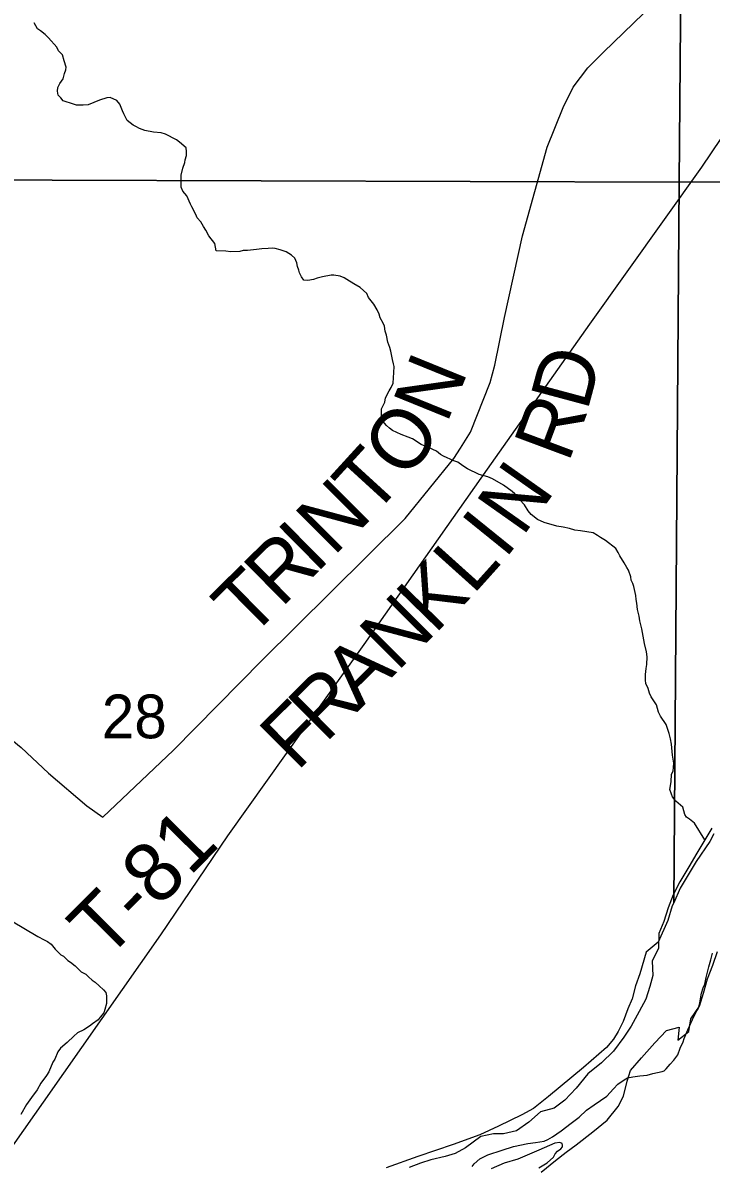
# Model space of a CAD drawing. Extents: x 0 to 34, y 0 to 22.
# Drawn here: x 4.533 to 5.191, y 16.193 to 17.286 of the extents above; entities that cross this region are included whole.
import ezdxf

# ---------------------------------------------------------------- set-up
doc = ezdxf.new("R2010")
doc.units = 0
for name, color, linetype in [('GM_X_Corporation', 7, 'Continuous'), ('GM_X_County_Road', 7, 'Continuous'), ('GM_X_County_Road_Text', 7, 'Continuous'), ('GM_X_Major_River', 7, 'Continuous'), ('GM_X_Minor_River', 7, 'Continuous'), ('GM_X_Rail_Line', 7, 'Continuous'), ('GM_X_Section_Text', 7, 'Continuous'), ('GM_X_Township_Road_Text', 7, 'Continuous')]:
    doc.layers.add(name, color=color, linetype=linetype)

msp = doc.modelspace()

# ---------------------------------------------------------------- linework, layer by layer
at = {"layer": 'GM_X_Corporation'}
msp.add_lwpolyline([(4.1647, 18.1352), (5.169, 18.1258), (5.1609, 17.1336), (4.1603, 17.1368)], close=True, dxfattribs=at)
for points in [[(5.3558, 17.3173), (5.3351, 17.273), (5.3274, 17.2459), (5.3164, 17.2139), (5.312, 17.203), (5.304, 17.1794), (5.3003, 17.1688), (5.2975, 17.1409), (5.2954, 17.1341), (5.1609, 17.1336), (5.169, 18.1258)], [(4.1603, 17.1368), (5.1609, 17.1336), (5.1556, 16.4443), (5.154, 16.4413), (5.15, 16.4274), (5.1408, 16.4067), (5.1292, 16.3971), (5.1231, 16.3764), (5.119, 16.3647), (5.1157, 16.3523), (5.1117, 16.3429), (5.1073, 16.3305), (5.1025, 16.3211), (5.0978, 16.3137), (5.0912, 16.3059), (5.0692, 16.2866), (5.0357, 16.2589), (5.0214, 16.2475), (5.0103, 16.2413), (4.9877, 16.2304), (4.9701, 16.2221), (4.9445, 16.2128), (4.9106, 16.2014), (4.8804, 16.1907)], [(5.1938, 16.5101), (5.1902, 16.503), (5.1769, 16.4836), (5.1616, 16.4582), (5.1556, 16.4443), (5.1609, 17.1336), (5.2954, 17.1341)], [(4.9626, 16.192), (4.9646, 16.1946), (4.97, 16.1994), (4.9777, 16.203), (4.9914, 16.2076), (5.0021, 16.2112), (5.0158, 16.2139), (5.0234, 16.2149), (5.0317, 16.2162), (5.0352, 16.2177), (5.0394, 16.2202), (5.0479, 16.2261), (5.0575, 16.2335), (5.0652, 16.239), (5.0721, 16.2457), (5.0794, 16.2508), (5.0856, 16.2552), (5.0914, 16.2593), (5.098, 16.2663), (5.1022, 16.2708), (5.108, 16.2748), (5.1114, 16.2766), (5.1164, 16.2777), (5.1232, 16.2787), (5.1301, 16.2793), (5.1354, 16.281), (5.1445, 16.2827), (5.1464, 16.2835), (5.1484, 16.2853), (5.1522, 16.2898), (5.1557, 16.2935), (5.1596, 16.2987), (5.1617, 16.3051), (5.1645, 16.3111), (5.1657, 16.3145), (5.1692, 16.3227), (5.1736, 16.3325), (5.1768, 16.3392), (5.1792, 16.3434), (5.1804, 16.3486), (5.1821, 16.3577), (5.1838, 16.363), (5.1853, 16.3663), (5.1866, 16.3727), (5.1891, 16.3829), (5.1911, 16.3897), (5.1928, 16.3961)], [(5.0266, 16.1906), (5.0343, 16.1953), (5.0405, 16.2009), (5.0421, 16.2039), (5.0444, 16.2065), (5.0475, 16.2087), (5.049, 16.2106), (5.0491, 16.2124), (5.0487, 16.214), (5.0465, 16.2148), (5.0419, 16.2141), (5.0266, 16.2076), (5.0064, 16.199), (4.9934, 16.1951), (4.9808, 16.1897)]]:
    msp.add_lwpolyline(points, dxfattribs=at)
at = {"layer": 'GM_X_County_Road'}
for points in [[(4.9515, 16.8793), (4.961, 16.8946), (4.98, 16.9422), (4.9843, 16.9585), (4.9937, 17.0044), (5.0109, 17.0823), (5.0344, 17.1672), (5.0498, 17.2051), (5.0592, 17.2245), (5.0732, 17.2431), (5.0882, 17.2581), (5.184, 17.3508)], [(4.6091, 16.5261), (4.6767, 16.5903), (4.7616, 16.6764), (4.827, 16.741), (4.8985, 16.8119), (4.9451, 16.8692), (4.9515, 16.8793)], [(3.7241, 16.5854), (3.9049, 16.5844), (4.0823, 16.5872), (4.1373, 16.59), (4.1698, 16.5932), (4.1944, 16.5988), (4.2309, 16.6077), (4.2593, 16.6207), (4.2867, 16.6246), (4.3422, 16.6223), (4.4404, 16.619), (4.5023, 16.6152), (4.5112, 16.6097), (4.522, 16.6), (4.5311, 16.5928), (4.5572, 16.5681), (4.5938, 16.5369), (4.6091, 16.5261)]]:
    msp.add_lwpolyline(points, dxfattribs=at)
at = {"layer": 'GM_X_Major_River'}
for points in [[(5.1919, 16.5155), (5.1853, 16.5046), (5.1778, 16.4918), (5.1699, 16.4787), (5.1613, 16.4644), (5.155, 16.452), (5.1502, 16.4395), (5.1461, 16.4263), (5.1413, 16.415), (5.141, 16.4007)], [(5.141, 16.4007), (5.135, 16.3884), (5.1357, 16.3747), (5.1328, 16.3641), (5.1287, 16.3521), (5.1226, 16.3401), (5.1147, 16.3263), (5.1079, 16.3158), (5.098, 16.3024), (5.0863, 16.291), (5.0735, 16.2807), (5.0621, 16.267), (5.0512, 16.2555), (5.0411, 16.2478), (5.0281, 16.2443), (5.0168, 16.2344), (5.0052, 16.226), (4.9926, 16.2233), (4.9831, 16.2232), (4.9709, 16.2205), (4.9561, 16.2098), (4.9465, 16.2044), (4.9369, 16.2016), (4.9232, 16.1982), (4.9132, 16.195), (4.9024, 16.1908)], [(5.0288, 16.1866), (5.0424, 16.1977), (5.0525, 16.2057), (5.0622, 16.2127), (5.0781, 16.2252), (5.092, 16.2362), (5.1023, 16.2492), (5.1075, 16.2593), (5.1109, 16.2736), (5.1142, 16.2838), (5.1248, 16.296), (5.1374, 16.3101), (5.1487, 16.322), (5.1609, 16.3251), (5.1595, 16.3129), (5.1699, 16.321), (5.1718, 16.3331), (5.1801, 16.3454), (5.1839, 16.3578), (5.188, 16.3714), (5.193, 16.3845), (5.1975, 16.3977)]]:
    msp.add_lwpolyline(points, dxfattribs=at)
at = {"layer": 'GM_X_Minor_River'}
for points in [[(4.572, 17.2499), (4.5705, 17.2556), (4.5667, 17.2595), (4.5652, 17.2629), (4.557, 17.2717), (4.554, 17.2751), (4.5495, 17.2786), (4.5465, 17.2805), (4.5435, 17.2862)], [(4.8875, 16.9599), (4.8864, 16.9641), (4.8849, 16.9721), (4.8838, 16.9755), (4.882, 16.9805), (4.8805, 16.9873), (4.8794, 16.9911), (4.8787, 16.996), (4.8776, 16.9987), (4.8746, 17.004), (4.8735, 17.0075), (4.8716, 17.0117), (4.8686, 17.017), (4.8634, 17.0235), (4.8619, 17.0273), (4.8555, 17.033), (4.8495, 17.0365), (4.8427, 17.0407), (4.8401, 17.0423), (4.8363, 17.0438), (4.8303, 17.0446), (4.8276, 17.0447), (4.8193, 17.0432), (4.8144, 17.0418), (4.8109, 17.0407), (4.8053, 17.0396), (4.8015, 17.04), (4.7992, 17.043), (4.7974, 17.0469), (4.7966, 17.0495), (4.7955, 17.0529), (4.7948, 17.0564), (4.7929, 17.0609), (4.7896, 17.064), (4.7847, 17.0671), (4.779, 17.069), (4.7741, 17.0702), (4.7715, 17.0706), (4.7673, 17.0703), (4.7612, 17.0699), (4.7563, 17.0692), (4.7476, 17.0685), (4.7435, 17.0682), (4.7404, 17.0675), (4.7317, 17.0672), (4.7268, 17.0676), (4.7177, 17.0681), (4.7163, 17.0749), (4.7107, 17.0825), (4.7077, 17.0879), (4.7054, 17.0913), (4.7028, 17.0959), (4.6994, 17.0997), (4.6983, 17.1028), (4.6942, 17.11), (4.6931, 17.1127), (4.6894, 17.1207), (4.6856, 17.1252), (4.6841, 17.1291), (4.6842, 17.1404), (4.6858, 17.1472), (4.6877, 17.1525), (4.6881, 17.1552), (4.6893, 17.1593), (4.6893, 17.1631), (4.689, 17.1666), (4.6826, 17.1719), (4.6796, 17.1742), (4.669, 17.1796), (4.6649, 17.1808), (4.6577, 17.1816), (4.6494, 17.1832), (4.6467, 17.184), (4.6441, 17.1852), (4.6407, 17.1871), (4.6381, 17.1883), (4.6324, 17.1929), (4.6309, 17.1959), (4.6291, 17.199), (4.628, 17.202), (4.6254, 17.2085), (4.6227, 17.2119), (4.6163, 17.2146), (4.6129, 17.2143), (4.6061, 17.2121), (4.5951, 17.2076), (4.5902, 17.2073), (4.5841, 17.2073), (4.5781, 17.2093), (4.5739, 17.2105), (4.5713, 17.2116), (4.569, 17.2143), (4.5664, 17.217), (4.5657, 17.2208), (4.5661, 17.2242), (4.568, 17.2283), (4.5711, 17.2325), (4.5726, 17.2378), (4.5738, 17.2412), (4.5742, 17.2438), (4.572, 17.2499)], [(5.1853, 16.5046), (5.1755, 16.5204), (5.1706, 16.5242), (5.1679, 16.5262), (5.1661, 16.5288), (5.1642, 16.5357), (5.1575, 16.5414), (5.1545, 16.5456), (5.1534, 16.5483), (5.1519, 16.5525), (5.1531, 16.56), (5.1535, 16.5672), (5.155, 16.5703), (5.1555, 16.5778), (5.1544, 16.5854), (5.1537, 16.5926), (5.1533, 16.5961), (5.1526, 16.601), (5.1511, 16.6063), (5.1497, 16.6109), (5.1482, 16.6147), (5.1429, 16.6227), (5.1411, 16.6265), (5.1392, 16.6337), (5.134, 16.6414), (5.1325, 16.6448), (5.131, 16.6494), (5.1288, 16.6539), (5.1284, 16.6573), (5.1285, 16.6627), (5.1293, 16.6683), (5.1297, 16.6721), (5.1301, 16.6797), (5.1294, 16.6843), (5.1276, 16.6922), (5.125, 16.7063), (5.1232, 16.7139), (5.1225, 16.7185), (5.121, 16.7249), (5.1203, 16.731), (5.1196, 16.7344), (5.1192, 16.7382), (5.1174, 16.7469), (5.1163, 16.7496), (5.1148, 16.753), (5.1144, 16.7561), (5.1122, 16.7625), (5.1107, 16.7652), (5.1081, 16.7694), (5.104, 16.7763), (5.1025, 16.7793), (5.1002, 16.7831), (5.0901, 16.7908), (5.0856, 16.7939), (5.0826, 16.7958), (5.0784, 16.7981), (5.0663, 16.8001), (5.061, 16.8009), (5.0558, 16.8025), (5.0497, 16.8037), (5.0437, 16.8045), (5.0316, 16.808), (5.0252, 16.8111), (5.0192, 16.8157), (5.0162, 16.8192), (5.0128, 16.8249), (5.0083, 16.8299), (5.0034, 16.8356), (5.0008, 16.8379), (4.9925, 16.8437), (4.982, 16.8498), (4.9775, 16.8518), (4.9692, 16.8541), (4.9582, 16.8595), (4.9537, 16.8622), (4.9488, 16.8657), (4.9451, 16.8672), (4.9353, 16.8715), (4.9322, 16.8731), (4.9285, 16.8765), (4.921, 16.88), (4.9176, 16.8812), (4.9138, 16.8827), (4.9055, 16.8881), (4.9014, 16.8896), (4.8946, 16.8924), (4.8863, 16.8962), (4.8836, 16.8982), (4.8806, 16.9008), (4.8765, 16.9058), (4.8758, 16.91), (4.8758, 16.9168), (4.8789, 16.9232), (4.8797, 16.9274), (4.8832, 16.9342), (4.8851, 16.9372), (4.887, 16.9414), (4.8878, 16.9516), (4.8879, 16.9573), (4.8875, 16.9599)], [(4.5217, 16.4271), (4.5469, 16.412), (4.5529, 16.4089), (4.5563, 16.4073), (4.5596, 16.4045), (4.5634, 16.3999), (4.5689, 16.3945), (4.5716, 16.3933), (4.5757, 16.389), (4.5783, 16.3875), (4.5828, 16.3839), (4.5884, 16.3781), (4.5929, 16.3758), (4.5955, 16.3734), (4.5989, 16.3703), (4.6019, 16.3684), (4.6056, 16.3649), (4.6097, 16.361), (4.6119, 16.3583), (4.6126, 16.3552), (4.6125, 16.348), (4.6112, 16.342), (4.61, 16.3389), (4.6065, 16.3348), (4.6046, 16.3322), (4.5992, 16.3285), (4.5965, 16.3263), (4.5911, 16.3226), (4.585, 16.3197), (4.5815, 16.3167), (4.5749, 16.3104), (4.5687, 16.3052), (4.566, 16.3015), (4.5632, 16.2947), (4.5612, 16.2917), (4.5576, 16.2826), (4.5553, 16.2789), (4.5498, 16.2718), (4.5463, 16.2654), (4.5408, 16.2579), (4.5361, 16.2511), (4.5306, 16.2418)]]:
    msp.add_lwpolyline(points, dxfattribs=at)
at = {"layer": 'GM_X_Rail_Line'}
msp.add_lwpolyline([(3.8337, 15.5051), (3.9125, 15.5684), (4.025, 15.6578), (4.1108, 15.7292), (4.2077, 15.8126), (4.2476, 15.8508), (4.2837, 15.8891), (4.3211, 15.9313), (4.3725, 16.0019), (4.4359, 16.0894), (4.4979, 16.1764), (4.5524, 16.2535), (4.6645, 16.4136), (4.7287, 16.5084), (4.8593, 16.6913), (4.9773, 16.8591), (5.0754, 16.9979), (5.1824, 17.1481), (5.2189, 17.2021), (5.2481, 17.2571), (5.2725, 17.3103)], dxfattribs=at)

# ---------------------------------------------------------------- texts
at = {"layer": 'GM_X_County_Road_Text'}
for s, rotation, p in [('D', 74.9853, (5.0728, 16.9137)), ('N', 67.8943, (4.9383, 16.9018)), ('R', 69.5145, (5.0547, 16.8643)), ('O', 52.0539, (4.899, 16.8475)), ('T', 47.6241, (4.8673, 16.8125)), ('N', 54.796, (5.0109, 16.7936)), ('N', 44.8581, (4.8297, 16.775)), ('I', 51.0756, (4.9938, 16.7722)), ('I', 44.6357, (4.813, 16.7585)), ('R', 44.6385, (4.7798, 16.7257)), ('L', 48.0608, (4.9633, 16.7381)), ('T', 44.6394, (4.7495, 16.6958)), ('K', 45.7316, (4.9267, 16.7005)), ('N', 45.0174, (4.8908, 16.6646)), ('A', 44.8714, (4.8553, 16.6292)), ('R', 44.857, (4.8222, 16.5963)), ('F', 44.8555, (4.795, 16.5692))]:
    msp.add_text(s, height=0.0568, rotation=rotation, dxfattribs=at).set_placement(p)
at = {"layer": 'GM_X_Section_Text'}
msp.add_text('28', height=0.04186, rotation=0, dxfattribs=at).set_placement((4.6081, 16.6016))
at = {"layer": 'GM_X_Township_Road_Text'}
msp.add_text('T-81', height=0.05682, rotation=45.2505, dxfattribs=at).set_placement((4.6119, 16.388))

doc.saveas('drawing.dxf')
